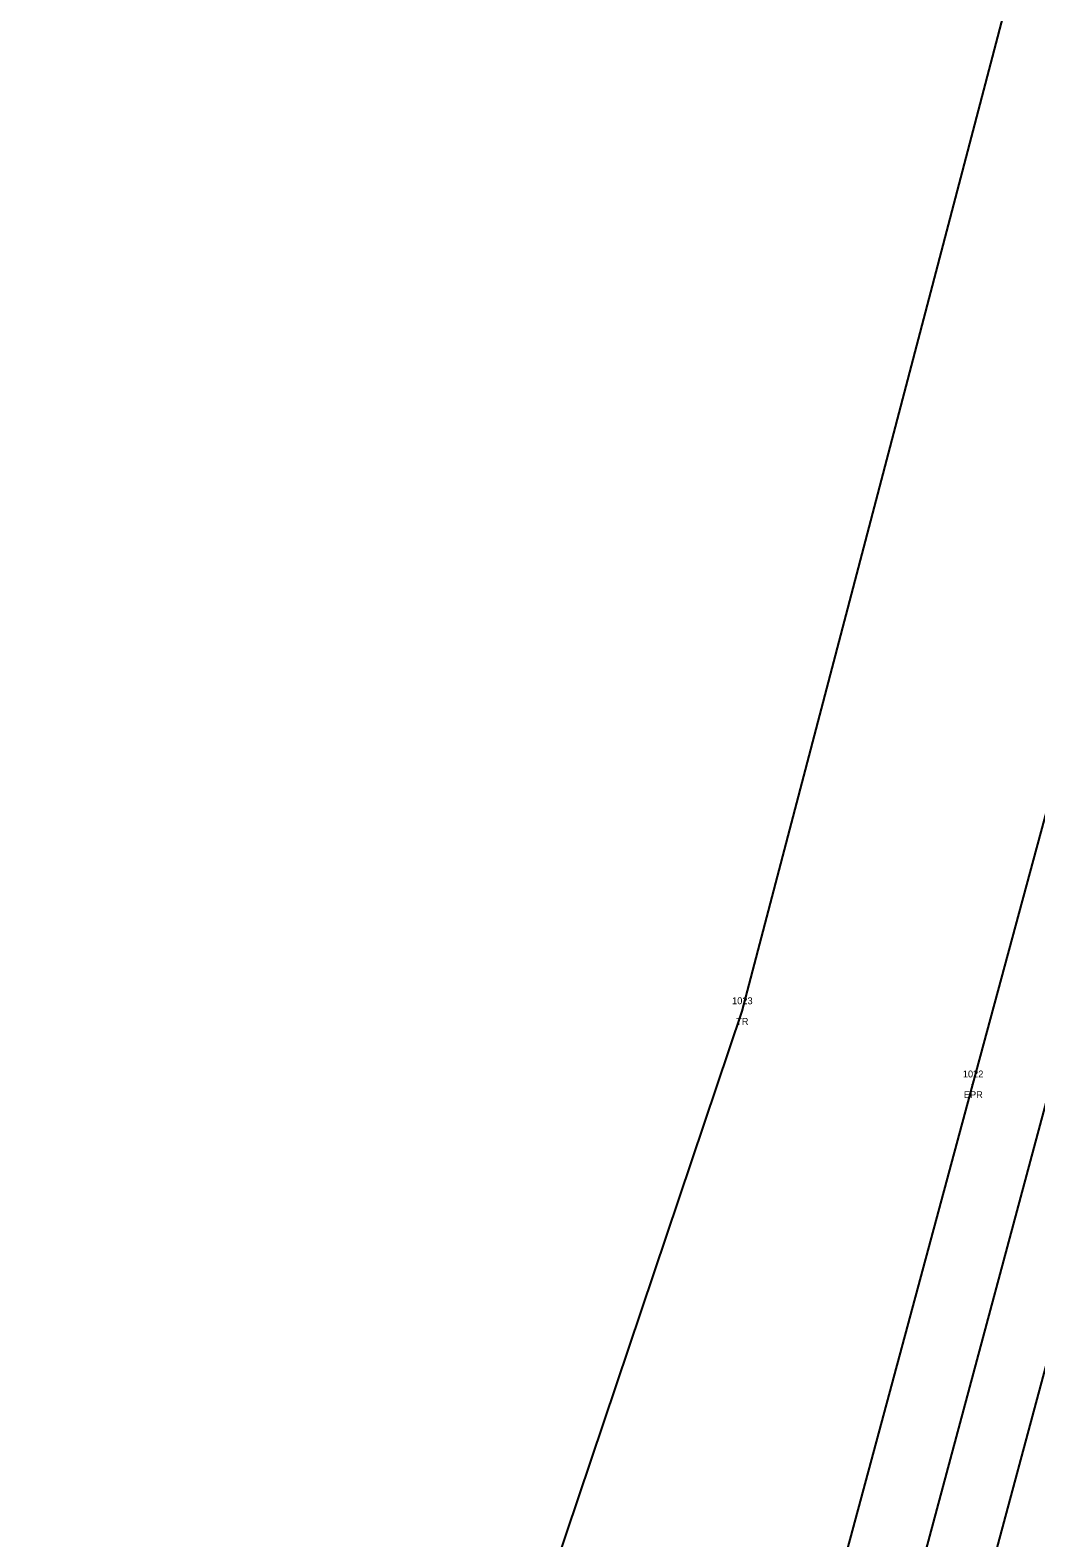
# Model space of a CAD drawing. Extents: x 2432632 to 2433497, y 684847 to 688233.
# Drawn here: x 2432885.8 to 2433031.5, y 687623.5 to 687841.9 of the extents above; entities that cross this region are included whole.
import ezdxf

# ---------------------------------------------------------------- set-up
doc = ezdxf.new("R2010")
doc.units = 0
for name, color, linetype in [('RD_EX_Road', 7, 'Continuous'), ('RD_EX_Road_txCode', 7, 'Continuous'), ('RD_EX_VEG', 7, 'Continuous'), ('RD_EX_VEG_txCode', 7, 'Continuous'), ('RD_HC_Cl', 7, 'Continuous'), ('RD_SMD_Locator', 7, 'Continuous')]:
    doc.layers.add(name, color=color, linetype=linetype)

msp = doc.modelspace()

# ---------------------------------------------------------------- linework, layer by layer
at = {"layer": 'RD_EX_Road'}
for points in [[(2433130.63, 688090.22), (2433103.18, 687988.73), (2433075.68, 687887.89), (2433049.83, 687790.75), (2433022.33, 687689.17), (2432994.76, 687586.82), (2432966.23, 687480.17), (2432943.15, 687390.42), (2432931.4, 687334.3), (2432921.83, 687273.88), (2432915.64, 687215.4), (2432913.86, 687159.12), (2432915.08, 687107.55), (2432919.97, 687053.4), (2432928.7, 686998.89), (2432946.77, 686924.59), (2432964.57, 686864), (2432997.3, 686766.34), (2433031.44, 686666.38), (2433066.06, 686565.78), (2433098.73, 686469.74)], [(2433151.11, 688085.43), (2433123.35, 687982.08), (2433096.36, 687882.07), (2433070.62, 687785.25), (2433042.64, 687684.31), (2433015.24, 687582.49), (2432986.34, 687474.01), (2432964, 687384.38)]]:
    msp.add_lwpolyline(points, dxfattribs=at)
at = {"layer": 'RD_EX_VEG'}
msp.add_lwpolyline([(2433112.43, 688094.61), (2433041.17, 687898.89), (2432988.9, 687699.78), (2432947.96, 687578.08), (2432935.9, 687556.87), (2432944.3, 687538.7), (2432913.88, 687397.98), (2432902.4, 687330.02), (2432885.78, 687157.56), (2432894.43, 687032.93), (2432918.07, 686924.4), (2432974.73, 686759.54), (2433073.82, 686456.42), (2433099.9, 686365.23), (2433115.47, 686257.21), (2433114.64, 686158.77), (2433095.68, 686092.78)], dxfattribs=at)
at = {"layer": 'RD_HC_Cl'}
msp.add_line((2433140.58, 688087.72), (2432956.34, 687400.83), dxfattribs=at)
at = {"layer": 'RD_SMD_Locator'}
for centre in [(2432988.9, 687699.78), (2433022.33, 687689.17)]:
    msp.add_circle(centre, 0.001, dxfattribs=at)

# ---------------------------------------------------------------- texts
at = {"layer": 'RD_EX_Road_txCode'}
for s, p in [('1022', (2433020.95, 687690.17)), ('EPR', (2433021.1, 687687.17))]:
    msp.add_text(s, height=1, dxfattribs=at).set_placement(p)
at = {"layer": 'RD_EX_VEG_txCode'}
for s, p in [('1023', (2432987.51, 687700.78)), ('TR', (2432988.1, 687697.78))]:
    msp.add_text(s, height=1, dxfattribs=at).set_placement(p)

doc.saveas('drawing.dxf')
